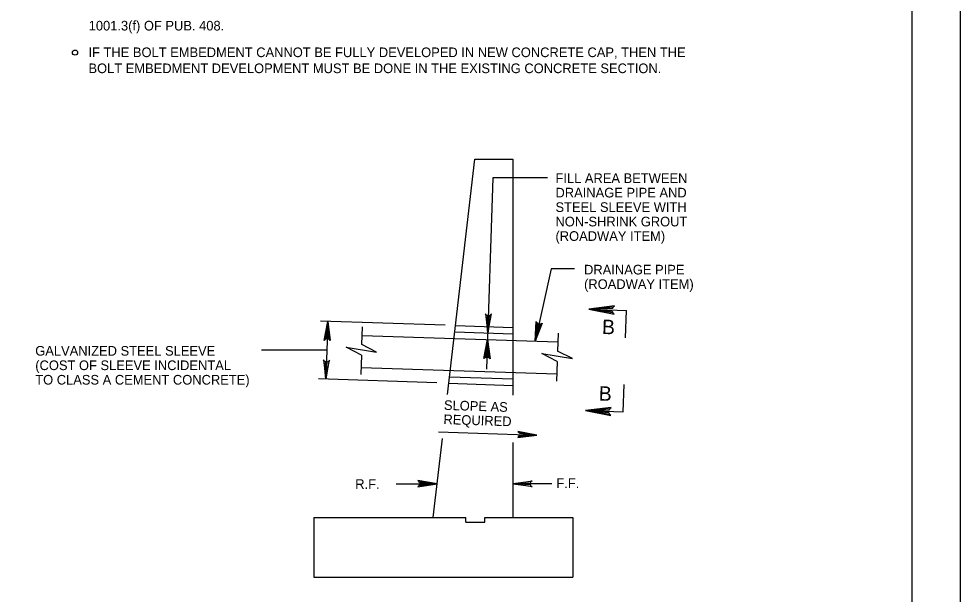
# Model space of a CAD drawing. Extents: x 235 to 2276, y 116 to 1308.
# Drawn here: x 1968.8 to 2261.4, y 944.9 to 1123.9 of the extents above; entities that cross this region are included whole.
import ezdxf

# ---------------------------------------------------------------- set-up
doc = ezdxf.new("R2010")
doc.units = 0
doc.layers.add('1', color=7, linetype='Continuous')
doc.layers.add('PLT-BNDY', color=7, linetype='Continuous')

msp = doc.modelspace()

# ---------------------------------------------------------------- linework, layer by layer
at = {"layer": '1'}
for p, q in [((2246.42, 1289.41), (2246.42, 725.41)), ((2102.04, 1007.05), (2110.49, 1080.19)), ((2110.49, 1080.19), (2122.37, 1080.19)), ((2122.37, 1080.19), (2122.37, 1006.79)), ((2116.16, 1074.4), (2114.2, 1014.9)), ((2133.17, 1074.4), (2116.16, 1074.4)), ((2134.24, 1046.07), (2129.26, 1023.65)), ((2141.49, 1046.07), (2134.24, 1046.07)), ((2145.93, 1033.58), (2157.67, 1033.19)), ((2157.39, 1024.66), (2157.67, 1033.19)), ((2101.28, 1028.57), (2062.5, 1029.84)), ((2064.82, 1029.77), (2064.23, 1011.78)), ((2075.38, 1022.54), (2075.57, 1028.12)), ((2104.52, 1028.46), (2122.37, 1027.88)), ((2075.48, 1025.41), (2136.37, 1023.41)), ((2104.28, 1026.47), (2122.37, 1025.87)), ((2136.46, 1026.12), (2136.28, 1020.54)), ((2064.52, 1020.77), (2044.22, 1020.77)), ((2075.27, 1019.25), (2075.08, 1013.22)), ((2136.17, 1017.25), (2135.97, 1011.22)), ((2075.15, 1015.42), (2136.04, 1013.42)), ((2098.75, 1010.64), (2061.91, 1011.85)), ((2102.44, 1010.52), (2122.37, 1009.87)), ((2102.67, 1012.51), (2122.37, 1011.87)), ((2156.63, 1001.61), (2156.91, 1010.15)), ((2144.89, 1002), (2156.63, 1001.61)), ((2099.22, 995.43), (2129.84, 994.42)), ((2097.62, 968.81), (2100.46, 993.35)), ((2122.37, 992.14), (2122.37, 968.81)), ((2086.07, 979.29), (2098.83, 979.29)), ((2134.45, 979.28), (2122.37, 979.28)), ((2060.49, 968.81), (2060.49, 950.19)), ((2060.49, 968.81), (2107.74, 968.81)), ((2107.74, 967.31), (2107.74, 968.81)), ((2113.62, 968.81), (2140.99, 968.81)), ((2113.62, 967.31), (2113.62, 968.81)), ((2140.99, 968.81), (2140.99, 950.19)), ((2107.74, 967.31), (2113.62, 967.31)), ((2060.49, 950.19), (2140.99, 950.19))]:
    msp.add_line(p, q, dxfattribs=at)
for points in [[(2153.57, 1034.27), (2153.27, 1033.72), (2145.93, 1033.58), (2153.57, 1034.27), (2153.97, 1034.59), (2145.93, 1033.58), (2153.23, 1032.96), (2153.48, 1032.4), (2145.93, 1033.58), (2153.88, 1032.03), (2153.48, 1032.4)], [(2114.05, 1031.83), (2114.45, 1031.6), (2114.57, 1026.13), (2114.05, 1031.83), (2113.81, 1032.13), (2114.57, 1026.13), (2115.02, 1031.58), (2115.43, 1031.76), (2114.57, 1026.13), (2115.72, 1032.06), (2115.43, 1031.76)], [(2063.92, 1024.12), (2064.34, 1024.31), (2064.82, 1029.77), (2063.92, 1024.12), (2063.66, 1023.83), (2064.82, 1029.77), (2064.91, 1024.3), (2065.31, 1024.09), (2064.82, 1029.77), (2065.57, 1023.77), (2065.31, 1024.09)], [(2131.19, 1029.03), (2130.74, 1028.92), (2129.26, 1023.65), (2131.19, 1029.03), (2131.49, 1029.26), (2129.26, 1023.65), (2130.18, 1029.04), (2129.83, 1029.32), (2129.26, 1023.65), (2129.63, 1029.68), (2129.83, 1029.32)], [(2075.27, 1019.25), (2070.49, 1021.78), (2079.96, 1020.18), (2075.38, 1022.54)], [(2113.61, 1018.48), (2114.03, 1018.68), (2114.51, 1024.13), (2113.61, 1018.48), (2113.35, 1018.2), (2114.51, 1024.13), (2114.6, 1018.67), (2115, 1018.45), (2114.51, 1024.13), (2115.26, 1018.14), (2115, 1018.45)], [(2136.17, 1017.25), (2131.39, 1019.78), (2140.86, 1018.18), (2136.28, 1020.54)], [(2063.7, 1017.47), (2064.1, 1017.25), (2064.23, 1011.78), (2063.7, 1017.47), (2063.46, 1017.77), (2064.23, 1011.78), (2064.67, 1017.22), (2065.09, 1017.41), (2064.23, 1011.78), (2065.37, 1017.71), (2065.09, 1017.41)], [(2152.53, 1002.69), (2152.23, 1002.15), (2144.89, 1002), (2152.53, 1002.69), (2152.93, 1003.01), (2144.89, 1002), (2152.2, 1001.38), (2152.44, 1000.83), (2144.89, 1002), (2152.84, 1000.45), (2152.44, 1000.83)], [(2124.15, 993.9), (2124.37, 994.3), (2129.84, 994.42), (2124.15, 993.9), (2123.85, 993.66), (2129.84, 994.42), (2124.39, 994.87), (2124.21, 995.29), (2129.84, 994.42), (2123.91, 995.57), (2124.21, 995.29)], [(2093.16, 978.58), (2093.37, 978.99), (2098.83, 979.29), (2093.16, 978.58), (2092.86, 978.33), (2098.83, 979.29), (2093.37, 979.56), (2093.17, 979.97), (2098.83, 979.29), (2092.86, 980.24), (2093.17, 979.97)], [(2128.05, 978.57), (2127.83, 978.98), (2122.37, 979.28), (2128.05, 978.57), (2128.34, 978.32), (2122.37, 979.28), (2127.83, 979.55), (2128.03, 979.96), (2122.37, 979.28), (2128.34, 980.23), (2128.03, 979.96)]]:
    msp.add_lwpolyline(points, dxfattribs=at)
msp.add_circle((1986.23, 1113.35), 0.804, dxfattribs=at)
at = {"layer": 'PLT-BNDY'}
msp.add_lwpolyline([(1420.42, 1304.41), (2261.42, 1304.41), (2261.42, 710.41), (1420.42, 710.41)], close=True, dxfattribs=at)

# ---------------------------------------------------------------- texts
at = {"layer": '1'}
for s, p in [('1001.3(f) OF PUB. 408.', (1990.48, 1120.22)), ('IF THE BOLT EMBEDMENT CANNOT BE FULLY DEVELOPED IN NEW CONCRETE CAP, THEN THE', (1990.41, 1111.94)), ('BOLT EMBEDMENT DEVELOPMENT MUST BE DONE IN THE EXISTING CONCRETE SECTION.', (1990.41, 1106.96)), ('FILL AREA BETWEEN', (2135.6, 1072.8)), ('DRAINAGE PIPE AND', (2135.6, 1068.3)), ('STEEL SLEEVE WITH', (2135.6, 1063.8)), ('NON-SHRINK GROUT', (2135.6, 1059.3)), ('(ROADWAY ITEM)', (2135.6, 1054.8)), ('DRAINAGE PIPE', (2144.49, 1044.35)), ('(ROADWAY ITEM)', (2144.49, 1039.85)), ('GALVANIZED STEEL SLEEVE', (1973.87, 1019.11)), ('(COST OF SLEEVE INCIDENTAL', (1973.87, 1014.61)), ('TO CLASS A CEMENT CONCRETE)', (1973.87, 1010.11)), ('R.F.', (2073.35, 977.68)), ('F.F.', (2135.87, 977.93))]:
    msp.add_text(s, height=3, dxfattribs=at).set_placement(p)
for s, height, p in [('B', 4.5, (2150.01, 1025.85)), ('B', 4.5, (2149.01, 1005.14)), ('SLOPE AS', 3, (2100.89, 1002.26)), ('REQUIRED', 3, (2100.74, 997.83))]:
    msp.add_text(s, height=height, rotation=358.1189, dxfattribs=at).set_placement(p)

doc.saveas('drawing.dxf')
